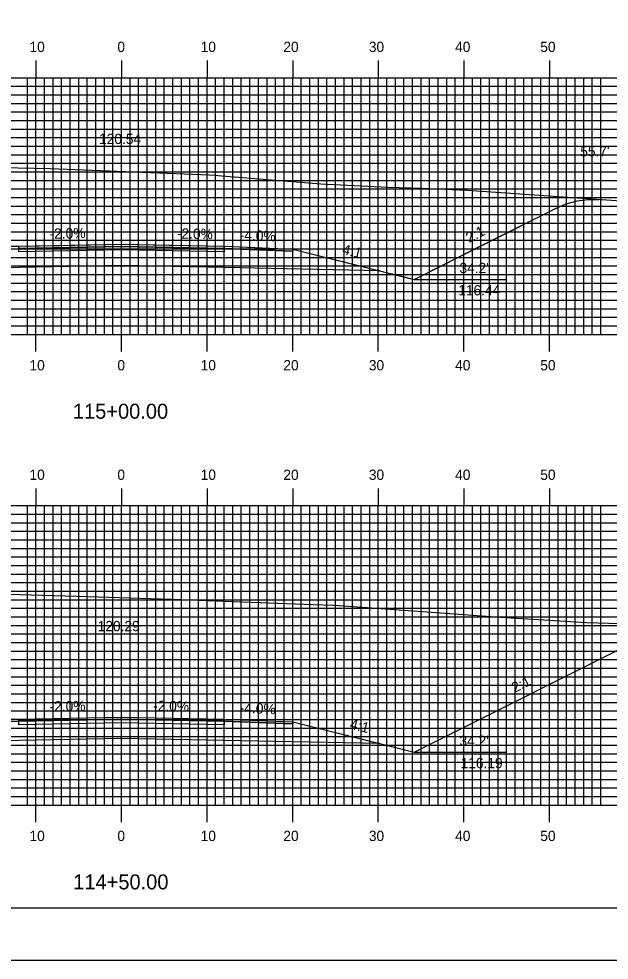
# Model space of a CAD drawing. Extents: x 1770842 to 1771185, y 442591 to 442811.
# Drawn here: x 1770995.6 to 1771064.5, y 442590.5 to 442700.5 of the extents above; entities that cross this region are included whole.
import ezdxf

# ---------------------------------------------------------------- set-up
doc = ezdxf.new("R2010")
doc.units = 0
for name, color, linetype in [('ANNOTATION', 7, 'Continuous'), ('BORDER', 7, 'Continuous'), ('D_Roadway_Centerline', 7, 'Continuous'), ('D_Roadway_Centerline_Text', 7, 'Continuous'), ('D_Roadway_Edge_Shoulder', 7, 'Continuous'), ('D_Roadway_Edge_TW', 7, 'Continuous'), ('D_Roadway_Pavement', 7, 'Continuous'), ('D_Roadway_SlopeLines', 7, 'Continuous'), ('D_Roadway_SubGrade', 7, 'Continuous'), ('D_Text_Standard', 7, 'Continuous'), ('H_V ANNOTATION', 7, 'Continuous'), ('MAJOR', 7, 'Continuous'), ('MINOR', 7, 'Continuous'), ('PDRAIN', 7, 'Continuous'), ('PLOT BOUNDARY', 7, 'Continuous'), ('S_Roadway_Centerline', 7, 'Continuous')]:
    doc.layers.add(name, color=color, linetype=linetype)

msp = doc.modelspace()

# ---------------------------------------------------------------- linework, layer by layer
at = {"layer": 'BORDER'}
msp.add_lwpolyline([(1770857.95, 442596.67), (1771177.95, 442596.67), (1771177.95, 442806.67), (1770857.95, 442806.67)], close=True, dxfattribs=at)
at = {"layer": 'D_Roadway_Centerline'}
for points in [[(1770987.55, 442673.65), (1770995.55, 442673.97), (1771000.3, 442674.06), (1771007.55, 442674.21), (1771013.12, 442674.09), (1771019.55, 442673.97), (1771027.55, 442673.65), (1771037.73, 442671.1), (1771039.96, 442670.54), (1771041.73, 442670.1), (1771049.24, 442673.86), (1771058.27, 442678.38), (1771059.52, 442678.91), (1771060.77, 442679.27), (1771062.02, 442679.45), (1771062.42, 442679.45), (1771063.27, 442679.45)], [(1770928.14, 442636.32), (1770928.6, 442636.27), (1770929.39, 442636.2), (1770930.36, 442635.99), (1770930.64, 442635.93), (1770931.48, 442635.66), (1770931.89, 442635.53), (1770933.14, 442634.97), (1770933.14, 442634.97), (1770955.81, 442623.64), (1770973.37, 442614.86), (1770973.38, 442614.85), (1770977.38, 442615.85), (1770977.38, 442615.85), (1770987.55, 442618.4), (1770995.55, 442618.72), (1771007.55, 442618.96), (1771019.55, 442618.72), (1771027.55, 442618.4), (1771027.55, 442618.4), (1771037.73, 442615.85), (1771041.73, 442614.85), (1771041.74, 442614.86), (1771068.97, 442628.47)]]:
    msp.add_lwpolyline(points, dxfattribs=at)
at = {"layer": 'D_Roadway_Edge_Shoulder'}
for points in [[(1770995.55, 442673.97), (1770987.55, 442673.65), (1770987.55, 442673.4), (1770995.55, 442673.72)], [(1771019.55, 442673.97), (1771027.55, 442673.65), (1771027.55, 442673.4), (1771019.55, 442673.72)], [(1770995.55, 442618.72), (1770987.55, 442618.4), (1770987.55, 442618.15), (1770995.55, 442618.47)], [(1771019.55, 442618.72), (1771027.55, 442618.4), (1771027.55, 442618.15), (1771019.55, 442618.47)]]:
    msp.add_lwpolyline(points, close=True, dxfattribs=at)
at = {"layer": 'D_Roadway_Edge_TW'}
for points in [[(1770995.55, 442673.72), (1770995.55, 442673.97), (1771007.55, 442674.21), (1771019.55, 442673.97), (1771019.55, 442673.72), (1771007.55, 442673.96)], [(1770995.55, 442618.47), (1770995.55, 442618.72), (1771007.55, 442618.96), (1771019.55, 442618.72), (1771019.55, 442618.47), (1771007.55, 442618.71)]]:
    msp.add_lwpolyline(points, close=True, dxfattribs=at)
at = {"layer": 'D_Roadway_Pavement'}
for points in [[(1770995.55, 442673.3), (1770995.55, 442673.72), (1771007.55, 442673.96), (1771019.55, 442673.72), (1771019.55, 442673.3), (1771007.55, 442673.54)], [(1770995.55, 442618.05), (1770995.55, 442618.47), (1771007.55, 442618.71), (1771019.55, 442618.47), (1771019.55, 442618.05), (1771007.55, 442618.29)]]:
    msp.add_lwpolyline(points, close=True, dxfattribs=at)
at = {"layer": 'D_Roadway_SlopeLines'}
for points in [[(1771041.73, 442670.1), (1771058.27, 442678.38), (1771059.52, 442678.91), (1771060.77, 442679.27), (1771062.02, 442679.45), (1771063.27, 442679.45)], [(1771027.55, 442673.65), (1771041.73, 442670.1)], [(1771041.73, 442614.85), (1771068.97, 442628.47), (1771070.22, 442629.02), (1771071.47, 442629.4), (1771072.72, 442629.62), (1771073.97, 442629.67)], [(1771027.55, 442618.4), (1771041.73, 442614.85)]]:
    msp.add_lwpolyline(points, dxfattribs=at)
at = {"layer": 'D_Roadway_SubGrade'}
for points in [[(1770995.55, 442671.47), (1770977.38, 442671.1), (1770987.55, 442673.65), (1770987.55, 442673.4), (1770995.55, 442673.72), (1771007.55, 442673.96), (1771019.55, 442673.72), (1771027.55, 442673.4), (1771027.55, 442673.65), (1771037.73, 442671.1), (1771019.55, 442671.47), (1771007.55, 442671.71)], [(1770995.55, 442616.22), (1770977.38, 442615.85), (1770987.55, 442618.4), (1770987.55, 442618.15), (1770995.55, 442618.47), (1771007.55, 442618.71), (1771019.55, 442618.47), (1771027.55, 442618.15), (1771027.55, 442618.4), (1771037.73, 442615.85), (1771019.55, 442616.22), (1771007.55, 442616.46)]]:
    msp.add_lwpolyline(points, close=True, dxfattribs=at)
at = {"layer": 'MAJOR'}
for p, q in [((1770997.55, 442695.67), (1770997.55, 442693.67)), ((1771007.55, 442695.67), (1771007.55, 442693.67)), ((1771017.55, 442695.67), (1771017.55, 442693.67)), ((1771027.55, 442695.67), (1771027.55, 442693.67)), ((1771037.55, 442695.67), (1771037.55, 442693.67)), ((1771047.55, 442695.67), (1771047.55, 442693.67)), ((1771057.55, 442695.67), (1771057.55, 442693.67)), ((1770867.55, 442693.67), (1771147.55, 442693.67)), ((1770867.55, 442693.67), (1771147.55, 442693.67)), ((1770997.55, 442663.67), (1770997.55, 442693.67)), ((1771007.55, 442663.67), (1771007.55, 442693.67)), ((1771017.55, 442663.67), (1771017.55, 442693.67)), ((1771027.55, 442663.67), (1771027.55, 442693.67)), ((1771037.55, 442663.67), (1771037.55, 442693.67)), ((1771047.55, 442663.67), (1771047.55, 442693.67)), ((1771057.55, 442663.67), (1771057.55, 442693.67)), ((1770867.55, 442688.67), (1771147.55, 442688.67)), ((1770867.55, 442683.67), (1771147.55, 442683.67)), ((1770867.55, 442678.67), (1771147.55, 442678.67)), ((1770867.55, 442673.67), (1771147.55, 442673.67)), ((1770867.55, 442668.67), (1771147.55, 442668.67)), ((1770867.55, 442663.67), (1771147.55, 442663.67)), ((1770867.55, 442663.67), (1771147.55, 442663.67)), ((1770997.55, 442661.66), (1770997.55, 442663.67)), ((1771007.55, 442661.66), (1771007.55, 442663.67)), ((1771017.55, 442661.66), (1771017.55, 442663.67)), ((1771027.55, 442661.66), (1771027.55, 442663.67)), ((1771037.55, 442661.66), (1771037.55, 442663.67)), ((1771047.55, 442661.66), (1771047.55, 442663.67)), ((1771057.55, 442661.66), (1771057.55, 442663.67)), ((1770997.55, 442645.67), (1770997.55, 442643.67)), ((1771007.55, 442645.67), (1771007.55, 442643.67)), ((1771017.55, 442645.67), (1771017.55, 442643.67)), ((1771027.55, 442645.67), (1771027.55, 442643.67)), ((1771037.55, 442645.67), (1771037.55, 442643.67)), ((1771047.55, 442645.67), (1771047.55, 442643.67)), ((1771057.55, 442645.67), (1771057.55, 442643.67)), ((1770867.55, 442643.67), (1771147.55, 442643.67)), ((1770867.55, 442643.67), (1771147.55, 442643.67)), ((1770997.55, 442608.67), (1770997.55, 442643.67)), ((1771007.55, 442608.67), (1771007.55, 442643.67)), ((1771017.55, 442608.67), (1771017.55, 442643.67)), ((1771027.55, 442608.67), (1771027.55, 442643.67)), ((1771037.55, 442608.67), (1771037.55, 442643.67)), ((1771047.55, 442608.67), (1771047.55, 442643.67)), ((1771057.55, 442608.67), (1771057.55, 442643.67)), ((1770867.55, 442638.67), (1771147.55, 442638.67)), ((1770867.55, 442633.67), (1771147.55, 442633.67)), ((1770867.55, 442628.67), (1771147.55, 442628.67)), ((1770867.55, 442623.67), (1771147.55, 442623.67)), ((1770867.55, 442618.67), (1771147.55, 442618.67)), ((1770867.55, 442613.67), (1771147.55, 442613.67)), ((1770867.55, 442608.67), (1771147.55, 442608.67)), ((1770867.55, 442608.67), (1771147.55, 442608.67)), ((1770997.55, 442606.66), (1770997.55, 442608.67)), ((1771007.55, 442606.66), (1771007.55, 442608.67)), ((1771017.55, 442606.66), (1771017.55, 442608.67)), ((1771027.55, 442606.66), (1771027.55, 442608.67)), ((1771037.55, 442606.66), (1771037.55, 442608.67)), ((1771047.55, 442606.66), (1771047.55, 442608.67)), ((1771057.55, 442606.66), (1771057.55, 442608.67))]:
    msp.add_line(p, q, dxfattribs=at)
at = {"layer": 'MINOR'}
for p, q in [((1770996.55, 442663.67), (1770996.55, 442693.67)), ((1770998.55, 442663.67), (1770998.55, 442693.67)), ((1770999.55, 442663.67), (1770999.55, 442693.67)), ((1771000.55, 442663.67), (1771000.55, 442693.67)), ((1771001.55, 442663.67), (1771001.55, 442693.67)), ((1771002.55, 442663.67), (1771002.55, 442693.67)), ((1771003.55, 442663.67), (1771003.55, 442693.67)), ((1771004.55, 442663.67), (1771004.55, 442693.67)), ((1771005.55, 442663.67), (1771005.55, 442693.67)), ((1771006.55, 442663.67), (1771006.55, 442693.67)), ((1771008.55, 442663.67), (1771008.55, 442693.67)), ((1771009.55, 442663.67), (1771009.55, 442693.67)), ((1771010.55, 442663.67), (1771010.55, 442693.67)), ((1771011.55, 442663.67), (1771011.55, 442693.67)), ((1771012.55, 442663.67), (1771012.55, 442693.67)), ((1771013.55, 442663.67), (1771013.55, 442693.67)), ((1771014.55, 442663.67), (1771014.55, 442693.67)), ((1771015.55, 442663.67), (1771015.55, 442693.67)), ((1771016.55, 442663.67), (1771016.55, 442693.67)), ((1771018.55, 442663.67), (1771018.55, 442693.67)), ((1771019.55, 442663.67), (1771019.55, 442693.67)), ((1771020.55, 442663.67), (1771020.55, 442693.67)), ((1771021.55, 442663.67), (1771021.55, 442693.67)), ((1771022.55, 442663.67), (1771022.55, 442693.67)), ((1771023.55, 442663.67), (1771023.55, 442693.67)), ((1771024.55, 442663.67), (1771024.55, 442693.67)), ((1771025.55, 442663.67), (1771025.55, 442693.67)), ((1771026.55, 442663.67), (1771026.55, 442693.67)), ((1771028.55, 442663.67), (1771028.55, 442693.67)), ((1771029.55, 442663.67), (1771029.55, 442693.67)), ((1771030.55, 442663.67), (1771030.55, 442693.67)), ((1771031.55, 442663.67), (1771031.55, 442693.67)), ((1771032.55, 442663.67), (1771032.55, 442693.67)), ((1771033.55, 442663.67), (1771033.55, 442693.67)), ((1771034.55, 442663.67), (1771034.55, 442693.67)), ((1771035.55, 442663.67), (1771035.55, 442693.67)), ((1771036.55, 442663.67), (1771036.55, 442693.67)), ((1771038.55, 442663.67), (1771038.55, 442693.67)), ((1771039.55, 442663.67), (1771039.55, 442693.67)), ((1771040.55, 442663.67), (1771040.55, 442693.67)), ((1771041.55, 442663.67), (1771041.55, 442693.67)), ((1771042.55, 442663.67), (1771042.55, 442693.67)), ((1771043.55, 442663.67), (1771043.55, 442693.67)), ((1771044.55, 442663.67), (1771044.55, 442693.67)), ((1771045.55, 442663.67), (1771045.55, 442693.67)), ((1771046.55, 442663.67), (1771046.55, 442693.67)), ((1771048.55, 442663.67), (1771048.55, 442693.67)), ((1771049.55, 442663.67), (1771049.55, 442693.67)), ((1771050.55, 442663.67), (1771050.55, 442693.67)), ((1771051.55, 442663.67), (1771051.55, 442693.67)), ((1771052.55, 442663.67), (1771052.55, 442693.67)), ((1771053.55, 442663.67), (1771053.55, 442693.67)), ((1771054.55, 442663.67), (1771054.55, 442693.67)), ((1771055.55, 442663.67), (1771055.55, 442693.67)), ((1771056.55, 442663.67), (1771056.55, 442693.67)), ((1771058.55, 442663.67), (1771058.55, 442693.67)), ((1771059.55, 442663.67), (1771059.55, 442693.67)), ((1771060.55, 442663.67), (1771060.55, 442693.67)), ((1771061.55, 442663.67), (1771061.55, 442693.67)), ((1771062.55, 442663.67), (1771062.55, 442693.67)), ((1771063.55, 442663.67), (1771063.55, 442693.67)), ((1770867.55, 442692.67), (1771147.55, 442692.67)), ((1770867.55, 442691.67), (1771147.55, 442691.67)), ((1770867.55, 442690.67), (1771147.55, 442690.67)), ((1770867.55, 442689.67), (1771147.55, 442689.67)), ((1770867.55, 442687.67), (1771147.55, 442687.67)), ((1770867.55, 442686.67), (1771147.55, 442686.67)), ((1770867.55, 442685.67), (1771147.55, 442685.67)), ((1770867.55, 442684.67), (1771147.55, 442684.67)), ((1770867.55, 442682.67), (1771147.55, 442682.67)), ((1770867.55, 442681.67), (1771147.55, 442681.67)), ((1770867.55, 442680.67), (1771147.55, 442680.67)), ((1770867.55, 442679.67), (1771147.55, 442679.67)), ((1770867.55, 442677.67), (1771147.55, 442677.67)), ((1770867.55, 442676.67), (1771147.55, 442676.67)), ((1770867.55, 442675.67), (1771147.55, 442675.67)), ((1770867.55, 442674.67), (1771147.55, 442674.67)), ((1770867.55, 442672.67), (1771147.55, 442672.67)), ((1770867.55, 442671.67), (1771147.55, 442671.67)), ((1770867.55, 442670.67), (1771147.55, 442670.67)), ((1770867.55, 442669.67), (1771147.55, 442669.67)), ((1770867.55, 442667.67), (1771147.55, 442667.67)), ((1770867.55, 442666.67), (1771147.55, 442666.67)), ((1770867.55, 442665.67), (1771147.55, 442665.67)), ((1770867.55, 442664.67), (1771147.55, 442664.67)), ((1770996.55, 442608.67), (1770996.55, 442643.67)), ((1770998.55, 442608.67), (1770998.55, 442643.67)), ((1770999.55, 442608.67), (1770999.55, 442643.67)), ((1771000.55, 442608.67), (1771000.55, 442643.67)), ((1771001.55, 442608.67), (1771001.55, 442643.67)), ((1771002.55, 442608.67), (1771002.55, 442643.67)), ((1771003.55, 442608.67), (1771003.55, 442643.67)), ((1771004.55, 442608.67), (1771004.55, 442643.67)), ((1771005.55, 442608.67), (1771005.55, 442643.67)), ((1771006.55, 442608.67), (1771006.55, 442643.67)), ((1771008.55, 442608.67), (1771008.55, 442643.67)), ((1771009.55, 442608.67), (1771009.55, 442643.67)), ((1771010.55, 442608.67), (1771010.55, 442643.67)), ((1771011.55, 442608.67), (1771011.55, 442643.67)), ((1771012.55, 442608.67), (1771012.55, 442643.67)), ((1771013.55, 442608.67), (1771013.55, 442643.67)), ((1771014.55, 442608.67), (1771014.55, 442643.67)), ((1771015.55, 442608.67), (1771015.55, 442643.67)), ((1771016.55, 442608.67), (1771016.55, 442643.67)), ((1771018.55, 442608.67), (1771018.55, 442643.67)), ((1771019.55, 442608.67), (1771019.55, 442643.67)), ((1771020.55, 442608.67), (1771020.55, 442643.67)), ((1771021.55, 442608.67), (1771021.55, 442643.67)), ((1771022.55, 442608.67), (1771022.55, 442643.67)), ((1771023.55, 442608.67), (1771023.55, 442643.67)), ((1771024.55, 442608.67), (1771024.55, 442643.67)), ((1771025.55, 442608.67), (1771025.55, 442643.67)), ((1771026.55, 442608.67), (1771026.55, 442643.67)), ((1771028.55, 442608.67), (1771028.55, 442643.67)), ((1771029.55, 442608.67), (1771029.55, 442643.67)), ((1771030.55, 442608.67), (1771030.55, 442643.67)), ((1771031.55, 442608.67), (1771031.55, 442643.67)), ((1771032.55, 442608.67), (1771032.55, 442643.67)), ((1771033.55, 442608.67), (1771033.55, 442643.67)), ((1771034.55, 442608.67), (1771034.55, 442643.67)), ((1771035.55, 442608.67), (1771035.55, 442643.67)), ((1771036.55, 442608.67), (1771036.55, 442643.67)), ((1771038.55, 442608.67), (1771038.55, 442643.67)), ((1771039.55, 442608.67), (1771039.55, 442643.67)), ((1771040.55, 442608.67), (1771040.55, 442643.67)), ((1771041.55, 442608.67), (1771041.55, 442643.67)), ((1771042.55, 442608.67), (1771042.55, 442643.67)), ((1771043.55, 442608.67), (1771043.55, 442643.67)), ((1771044.55, 442608.67), (1771044.55, 442643.67)), ((1771045.55, 442608.67), (1771045.55, 442643.67)), ((1771046.55, 442608.67), (1771046.55, 442643.67)), ((1771048.55, 442608.67), (1771048.55, 442643.67)), ((1771049.55, 442608.67), (1771049.55, 442643.67)), ((1771050.55, 442608.67), (1771050.55, 442643.67)), ((1771051.55, 442608.67), (1771051.55, 442643.67)), ((1771052.55, 442608.67), (1771052.55, 442643.67)), ((1771053.55, 442608.67), (1771053.55, 442643.67)), ((1771054.55, 442608.67), (1771054.55, 442643.67)), ((1771055.55, 442608.67), (1771055.55, 442643.67)), ((1771056.55, 442608.67), (1771056.55, 442643.67)), ((1771058.55, 442608.67), (1771058.55, 442643.67)), ((1771059.55, 442608.67), (1771059.55, 442643.67)), ((1771060.55, 442608.67), (1771060.55, 442643.67)), ((1771061.55, 442608.67), (1771061.55, 442643.67)), ((1771062.55, 442608.67), (1771062.55, 442643.67)), ((1771063.55, 442608.67), (1771063.55, 442643.67)), ((1770867.55, 442642.67), (1771147.55, 442642.67)), ((1770867.55, 442641.67), (1771147.55, 442641.67)), ((1770867.55, 442640.67), (1771147.55, 442640.67)), ((1770867.55, 442639.67), (1771147.55, 442639.67)), ((1770867.55, 442637.67), (1771147.55, 442637.67)), ((1770867.55, 442636.67), (1771147.55, 442636.67)), ((1770867.55, 442635.67), (1771147.55, 442635.67)), ((1770867.55, 442634.67), (1771147.55, 442634.67)), ((1770867.55, 442632.67), (1771147.55, 442632.67)), ((1770867.55, 442631.67), (1771147.55, 442631.67)), ((1770867.55, 442630.67), (1771147.55, 442630.67)), ((1770867.55, 442629.67), (1771147.55, 442629.67)), ((1770867.55, 442627.67), (1771147.55, 442627.67)), ((1770867.55, 442626.67), (1771147.55, 442626.67)), ((1770867.55, 442625.67), (1771147.55, 442625.67)), ((1770867.55, 442624.67), (1771147.55, 442624.67)), ((1770867.55, 442622.67), (1771147.55, 442622.67)), ((1770867.55, 442621.67), (1771147.55, 442621.67)), ((1770867.55, 442620.67), (1771147.55, 442620.67)), ((1770867.55, 442619.67), (1771147.55, 442619.67)), ((1770867.55, 442617.67), (1771147.55, 442617.67)), ((1770867.55, 442616.67), (1771147.55, 442616.67)), ((1770867.55, 442615.67), (1771147.55, 442615.67)), ((1770867.55, 442614.67), (1771147.55, 442614.67)), ((1770867.55, 442612.67), (1771147.55, 442612.67)), ((1770867.55, 442611.67), (1771147.55, 442611.67)), ((1770867.55, 442610.67), (1771147.55, 442610.67)), ((1770867.55, 442609.67), (1771147.55, 442609.67))]:
    msp.add_line(p, q, dxfattribs=at)
at = {"layer": 'PDRAIN'}
for p, q in [((1771041.73, 442670.1), (1771052.5, 442670.1)), ((1771041.73, 442614.85), (1771052.5, 442614.85))]:
    msp.add_line(p, q, dxfattribs=at)
at = {"layer": 'PLOT BOUNDARY'}
msp.add_lwpolyline([(1770841.77, 442590.55), (1771181.77, 442590.55), (1771181.77, 442810.55), (1770841.77, 442810.55)], close=True, dxfattribs=at)
at = {"layer": 'S_Roadway_Centerline'}
for points in [[(1770930.09, 442685.53), (1770939.79, 442684.95), (1770958.47, 442684.49), (1770960.13, 442684.42), (1770971.63, 442684.09), (1770979.3, 442683.69), (1770983.73, 442683.41), (1770989.74, 442683.24), (1770999.2, 442683.04), (1771017.78, 442682.3), (1771018.44, 442682.27), (1771018.58, 442682.27), (1771018.81, 442682.25), (1771030.84, 442681.26), (1771038.66, 442680.87), (1771042.63, 442680.75), (1771047.93, 442680.53), (1771065.88, 442679.27)], [(1770937.99, 442635.94), (1770944.06, 442635.42), (1770949.74, 442634.96), (1770953.65, 442634.66), (1770969.93, 442634.14), (1770972.75, 442634.05), (1770974.28, 442634), (1770985.56, 442633.61), (1770992.98, 442633.36), (1771003.62, 442633.05), (1771013.38, 442632.73), (1771029.95, 442632.11), (1771032.3, 442632.02), (1771033.55, 442631.96), (1771051.78, 442630.64), (1771056.29, 442630.34), (1771061.87, 442630), (1771072.36, 442629.7)]]:
    msp.add_lwpolyline(points, dxfattribs=at)

# ---------------------------------------------------------------- texts
at = {"layer": 'ANNOTATION'}
for s, rotation, p in [('-2.0%', 1.1458, (1770999.16, 442674.84)), ('-2.0%', 358.8543, (1771014.02, 442674.88)), ('-4.0%', 357.7094, (1771021.35, 442674.7)), ('2:1', 26.5661, (1771048.15, 442674.35)), ('4:1', 345.9616, (1771033.27, 442673.08)), ('2:1', 26.5647, (1771053.5, 442621.77)), ('-2.0%', 1.1458, (1770999.16, 442619.59)), ('-2.0%', 358.8542, (1771011.24, 442619.68)), ('-4.0%', 357.7092, (1771021.35, 442619.45)), ('4:1', 345.9621, (1771034.15, 442617.61))]:
    msp.add_text(s, height=1.2, rotation=rotation, dxfattribs=at).set_placement(p)
for s, p in [("34.2'", (1771047.04, 442670.83)), ('116.44', (1771046.89, 442668.23)), ("34.2'", (1771047.04, 442615.58)), ('116.19', (1771047.17, 442612.98))]:
    msp.add_text(s, height=1.2, dxfattribs=at).set_placement(p)
at = {"layer": 'D_Roadway_Centerline'}
for s, p in [('C', (1771007.55, 442674.21)), ('L', (1771007.55, 442674.2)), ('C', (1771007.55, 442618.96)), ('L', (1771007.55, 442618.95))]:
    msp.add_text(s, height=0.0146, dxfattribs=at).set_placement(p)
at = {"layer": 'D_Roadway_Centerline_Text'}
for s, p in [('120.54', (1771004.93, 442685.92)), ('120.29', (1771004.77, 442628.99))]:
    msp.add_text(s, height=1.2, dxfattribs=at).set_placement(p)
at = {"layer": 'D_Text_Standard'}
msp.add_text("55.7'", height=1.2, dxfattribs=at).set_placement((1771061.15, 442684.47))
at = {"layer": 'H_V ANNOTATION'}
for s, height, p in [('10', 1.2, (1770996.8, 442696.67)), ('0', 1.2, (1771007.07, 442696.67)), ('10', 1.2, (1771016.8, 442696.67)), ('20', 1.2, (1771026.46, 442696.67)), ('30', 1.2, (1771036.45, 442696.67)), ('40', 1.2, (1771046.53, 442696.67)), ('50', 1.2, (1771056.48, 442696.67)), ('10', 1.2, (1770996.8, 442659.47)), ('0', 1.2, (1771007.07, 442659.47)), ('10', 1.2, (1771016.8, 442659.47)), ('20', 1.2, (1771026.46, 442659.47)), ('30', 1.2, (1771036.45, 442659.47)), ('40', 1.2, (1771046.53, 442659.47)), ('50', 1.2, (1771056.48, 442659.47)), ('115+00.00', 1.75, (1771001.87, 442653.82)), ('10', 1.2, (1770996.8, 442646.67)), ('0', 1.2, (1771007.07, 442646.67)), ('10', 1.2, (1771016.8, 442646.67)), ('20', 1.2, (1771026.46, 442646.67)), ('30', 1.2, (1771036.45, 442646.67)), ('40', 1.2, (1771046.53, 442646.67)), ('50', 1.2, (1771056.48, 442646.67)), ('10', 1.2, (1770996.8, 442604.47)), ('0', 1.2, (1771007.07, 442604.47)), ('10', 1.2, (1771016.8, 442604.47)), ('20', 1.2, (1771026.46, 442604.47)), ('30', 1.2, (1771036.45, 442604.47)), ('40', 1.2, (1771046.53, 442604.47)), ('50', 1.2, (1771056.48, 442604.47)), ('114+50.00', 1.75, (1771001.91, 442598.82))]:
    msp.add_text(s, height=height, dxfattribs=at).set_placement(p)

doc.saveas('drawing.dxf')
